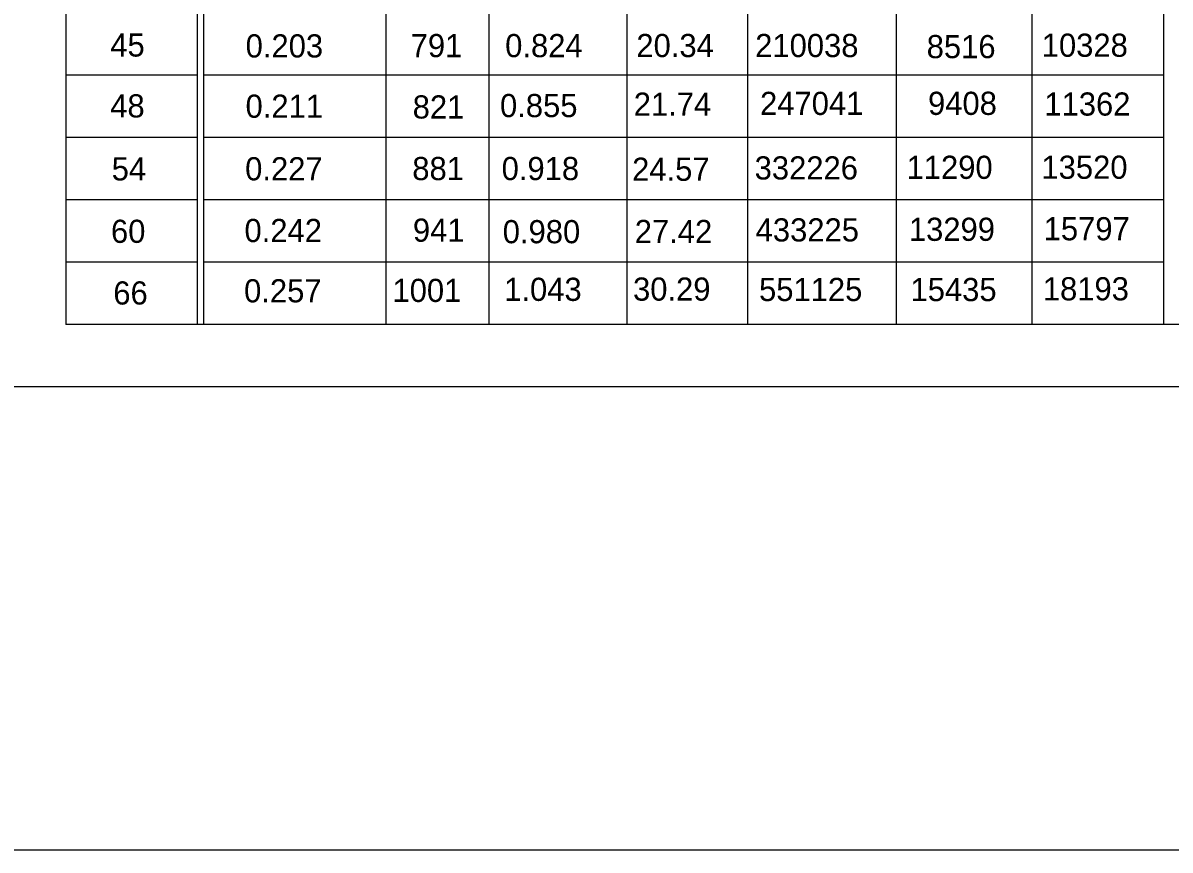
# Model space of a CAD drawing. Extents: x 635698 to 639877, y 296617 to 300175.
# Drawn here: x 639013.3 to 639162, y 299460.8 to 299568 of the extents above; entities that cross this region are included whole.
import ezdxf

# ---------------------------------------------------------------- set-up
doc = ezdxf.new("R2010")
doc.units = 0
for name, color, linetype in [('1', 7, 'Continuous'), ('2', 7, 'Continuous'), ('3', 7, 'Continuous')]:
    doc.layers.add(name, color=color, linetype=linetype)

msp = doc.modelspace()

# ---------------------------------------------------------------- linework, layer by layer
at = {"layer": '1'}
for p, q in [((639018.88, 299670.74), (639018.88, 299528.89)), ((639035.9, 299660.17), (639035.9, 299528.89)), ((639036.74, 299660.17), (639036.74, 299528.89)), ((639161.18, 299660.17), (639161.18, 299528.89)), ((639060.38, 299652.6), (639060.38, 299528.89)), ((639073.74, 299652.6), (639073.74, 299528.89)), ((639091.6, 299652.6), (639091.6, 299528.89)), ((639107.25, 299652.6), (639107.25, 299528.89)), ((639126.53, 299652.6), (639126.53, 299528.89)), ((639144.08, 299652.6), (639144.08, 299528.89)), ((639035.9, 299561.23), (639018.88, 299561.23)), ((639161.18, 299561.23), (639036.74, 299561.23)), ((639035.9, 299553.14), (639018.88, 299553.14)), ((639161.18, 299553.14), (639036.74, 299553.14)), ((639035.9, 299545.06), (639018.88, 299545.06)), ((639161.18, 299545.06), (639036.74, 299545.06)), ((639035.9, 299536.97), (639018.88, 299536.97)), ((639161.18, 299536.97), (639036.74, 299536.97)), ((639035.9, 299528.89), (639018.88, 299528.89)), ((639286.46, 299528.89), (639018.88, 299528.89)), ((639161.18, 299528.89), (639036.74, 299528.89)), ((639286.46, 299520.81), (638876.19, 299520.81))]:
    msp.add_line(p, q, dxfattribs=at)
at = {"layer": '2'}
msp.add_line((639628.3, 299460.8), (638842.3, 299460.8), dxfattribs=at)

# ---------------------------------------------------------------- texts
at = {"layer": '3'}
for s, height, p in [('45', 3, (639024.66, 299563.62)), ('0.203', 3.001, (639042.2, 299563.5)), ('791', 3.001, (639063.59, 299563.54)), ('0.824', 3.001, (639075.84, 299563.54)), ('20.34', 3.001, (639092.84, 299563.55)), ('210038', 3.001, (639108.24, 299563.55)), ('8516', 3.001, (639130.47, 299563.41)), ('10328', 3.001, (639145.38, 299563.59)), ('48', 3.001, (639024.65, 299555.73)), ('0.211', 3.001, (639042.19, 299555.69)), ('0.855', 3.001, (639075.17, 299555.77)), ('21.74', 3.001, (639092.5, 299555.95)), ('247041', 3.001, (639108.87, 299556.05)), ('9408', 3.001, (639130.64, 299556.06)), ('11362', 3.001, (639145.72, 299555.97)), ('821', 3.001, (639063.85, 299555.59)), ('54', 3.001, (639024.84, 299547.57)), ('0.227', 3.001, (639042.14, 299547.58)), ('881', 3.001, (639063.8, 299547.61)), ('0.918', 3.001, (639075.38, 299547.61)), ('24.57', 3.001, (639092.29, 299547.52)), ('332226', 3.001, (639108.17, 299547.69)), ('11290', 3.001, (639127.86, 299547.77)), ('13520', 3.001, (639145.34, 299547.78)), ('60', 3, (639024.75, 299539.48)), ('0.242', 3.001, (639042.05, 299539.58)), ('941', 3.001, (639063.88, 299539.63)), ('0.980', 3.001, (639075.52, 299539.43)), ('27.42', 3.001, (639092.63, 299539.45)), ('433225', 3.001, (639108.3, 299539.66)), ('13299', 3.001, (639128.16, 299539.74)), ('15797', 3.001, (639145.63, 299539.81)), ('1.043', 3.001, (639075.71, 299531.96)), ('30.29', 3.001, (639092.41, 299531.99)), ('551125', 3.001, (639108.74, 299531.94)), ('15435', 3.001, (639128.37, 299531.93)), ('18193', 3.001, (639145.52, 299532.03)), ('66', 3.001, (639025.05, 299531.49)), ('0.257', 3.001, (639042, 299531.77)), ('1001', 3.001, (639061.23, 299531.82))]:
    msp.add_text(s, height=height, dxfattribs=at).set_placement(p)

doc.saveas('drawing.dxf')
